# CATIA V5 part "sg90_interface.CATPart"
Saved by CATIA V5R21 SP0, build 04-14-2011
Part number: Part1
Bounding box of the stored display mesh (mm): x -4.25 to 4.25, y -4.232 to 4.232, z 0 to 4.2
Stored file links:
  Z:\Hobby\3d print_engraver\Eigene Designs\Modellbau\NerfDrop SG90\sg90_interface.CATPart
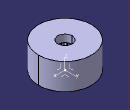
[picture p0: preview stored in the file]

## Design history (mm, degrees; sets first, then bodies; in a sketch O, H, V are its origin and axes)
AxisSystem1: origin (0, 0, 0), X (1, 0, 0), Y (0, 1, 0), Z (0, 0, 1)
Body1 (main body)
  Sketch1 on XY plane of AxisSystem1, origin (0, 0, 0), H (1, 0, 0), V (0, 1, 0)
    circle A1 centre (0, 0) radius 2.25
    circle A2 centre (0, 0) radius 4.25
    radius A1 = 2.25
    radius A2 = 4.25
  Pad1: profile Sketch1, direction (0, 0, 1), length 3
  Sketch2 on end face of Pad1, origin (0, 0, 3), H (1, 0, 0), V (0, 1, 0)
    construction circle A1 centre (0, 2.25) radius 0.25
    point P1 (0, 2.25)
    reference projected circle E1 centre (0, 0) radius 2.25 from edge [end face of Pad1 | face of Pad1 from Sketch1.A1]
    line L1 (0, 2) -> (0.433, 2)
    point P2 (0, 2)
    point P3 (0.433, 2)
    line L2 (0.433, 2) -> (0, 2.75)
    point P4 (0, 2.75)
    reference projected line E2 through (0, 0) direction (0, 1) from edge [YZ plane of AxisSystem1 | XY plane of AxisSystem1]
    point P7 (-0.433, 2)
    point P8 (0, 2)
    line L3 (0, 2) -> (-0.433, 2)
    point P9 (0, 2.75)
    line L4 (-0.433, 2) -> (0, 2.75)
    radius A1 = 0.25
    angle L1 L2 = 60
    coincidence: P1 V, E1 P1, P2 V, P4 V
    horizontal: L1 H
    tangency: L2 A1, L1 A1
    symmetry: P3 P7 E2, P2 P8 E2, L1 L3 E2, P4 P9 E2, L2 L4 E2
  Pocket1: profile Sketch2, direction (0, 0, -1), length 3
  CircPattern1: of Pocket1, instances 21, angular step 17.1429 {= 360.0*1 deg/CircPattern1.AngularNumber}, axis from edge [ZX plane of AxisSystem1 | YZ plane of AxisSystem1]
  Sketch3 on end face of Pad1, origin (0, 0, 3), H (1, 0, 0), V (0, 1, 0)
    projected circle E1 centre (0, 0) radius 4.25 from edge [face of Pad1 from Sketch1.A2 | end face of Pad1]
    circle A1 centre (0, 0) radius 1.15
    radius A1 = 1.15
  Pad2: profile Sketch3, direction (0, 0, 1), length 1.2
